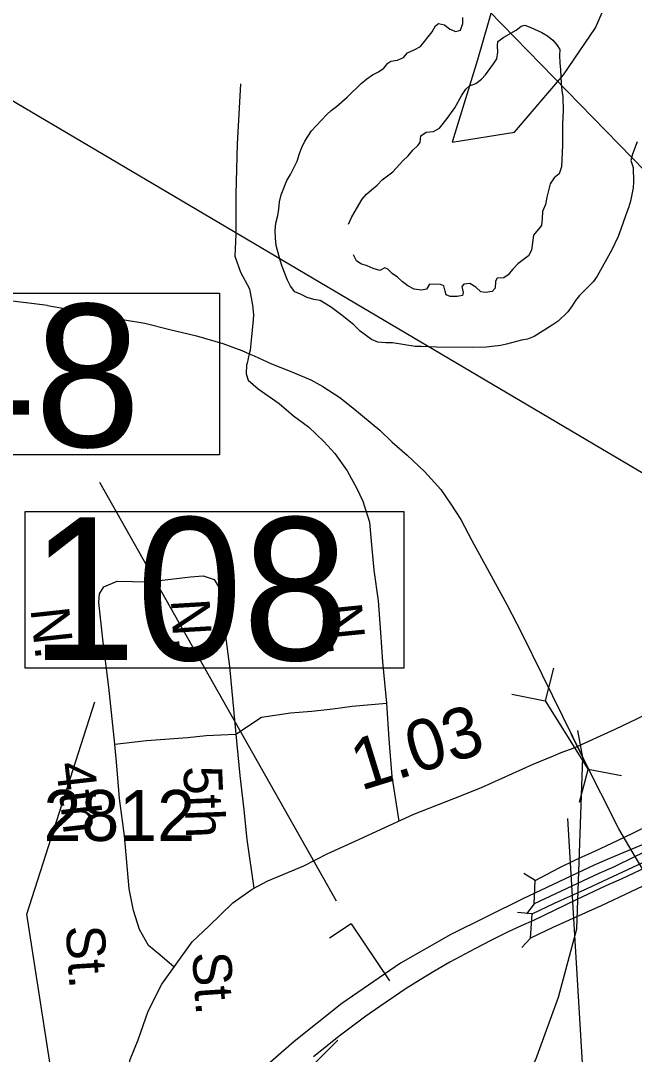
# Model space of a CAD drawing. Extents: x 2290055 to 2389491, y 66597 to 237875.
# Drawn here: x 2318095 to 2319601, y 184954 to 187491 of the extents above; entities that cross this region are included whole.
import ezdxf

# ---------------------------------------------------------------- set-up
doc = ezdxf.new("R2010")
doc.units = 0
for name, color, linetype in [('Exist Boundary Political City Limit New', 7, 'Continuous'), ('Exist Hydrographic Creek Double Shore', 7, 'Continuous'), ('Exist Hydrographic Island Shore', 7, 'Continuous'), ('Exist Railroad Mainline', 7, 'Continuous'), ('Exist Railroad Siding', 7, 'Continuous'), ('Exist Road Non-System Type 51', 7, 'Continuous'), ('Exist Road Non-System Type 51 Label', 7, 'Continuous'), ('Exist Road Primary US Divided Attributed', 7, 'Continuous'), ('Exist Road Primary US Ramp 1 Lane  Attributed', 7, 'Continuous'), ('Exist Road Primary US Structure Cantilever Sign CELL', 7, 'Continuous'), ('Exist Road Primary US Structure Cantilever Sign Number Label', 7, 'Continuous'), ('Exist Road Primary US Structure Standard Bridge Number Label', 7, 'Continuous'), ('Exist Road Secondary Mileage Hundredths English Label', 7, 'Continuous'), ('Exist Road Secondary Structure Culvert CELL', 7, 'Continuous'), ('Exist Road Secondary Type 51 Attributed', 7, 'Continuous'), ('Exist Road Secondary Type 51 Number Label', 7, 'Continuous'), ('Map Preparation Boundary City Limit Buffer Line', 7, 'Continuous')]:
    doc.layers.add(name, color=color, linetype=linetype)

msp = doc.modelspace()

# ---------------------------------------------------------------- linework, layer by layer
at = {"layer": 'Exist Boundary Political City Limit New'}
msp.add_lwpolyline([(2319108, 188879.4), (2319186.8, 188662.5), (2319224.5, 188585.7), (2319249.2, 188523.7), (2319282, 188432.2), (2319323.8, 188366.6), (2319377.2, 188199.9), (2319377.2, 188122.7), (2319369, 188044.2), (2319294.8, 187668), (2319216.2, 187395.2), (2319154.2, 187192.7), (2319307.2, 187217.5), (2319427, 187358), (2319505.5, 187473.8), (2319546.8, 187568.8), (2319601, 187700.6), (2319622.5, 187767.5)], dxfattribs=at)
at = {"layer": 'Exist Hydrographic Creek Double Shore'}
for points in [[(2319500.2, 186850.5), (2319477.5, 186827.3), (2319466.2, 186816.9), (2319456.5, 186804.8), (2319448.5, 186791.6), (2319438.2, 186776.8), (2319414, 186753.8), (2319399.2, 186743.6), (2319355, 186716.3), (2319339, 186709.4), (2319324, 186706.8), (2319287.7, 186697), (2319272.7, 186694.2), (2319238.7, 186689.9), (2319203, 186689.2), (2319115.7, 186690.1), (2319079, 186691.9), (2319063.7, 186691.8), (2319008, 186700.7), (2318991, 186700.8), (2318972, 186702.5), (2318956.2, 186709), (2318928.5, 186729.4), (2318912.5, 186745.1), (2318884.5, 186767.8), (2318858.2, 186787.5), (2318845, 186795.8), (2318830, 186804.2), (2318815, 186807.1), (2318798, 186811.5), (2318781.7, 186820), (2318768.2, 186825.8), (2318757.7, 186839.5), (2318750, 186854.5), (2318737.2, 186887.8), (2318731.7, 186903.1), (2318722.5, 186939.1), (2318720.5, 186957.7), (2318720, 186975.9), (2318721.2, 186994.5), (2318726, 187012.7), (2318729, 187028.9), (2318730.7, 187046.5), (2318734.2, 187064.1), (2318748.5, 187098.8), (2318757.5, 187113.3), (2318774, 187146.4), (2318779.5, 187165.1), (2318785, 187179.7), (2318792.7, 187195.1), (2318809.2, 187220.6), (2318845.5, 187260), (2318857.5, 187270.6), (2318870.5, 187280.5), (2318896.5, 187303.3), (2318931, 187337.2), (2318945, 187348.7), (2318959, 187357.9), (2318973.2, 187365.5), (2318986.7, 187374.2), (2318996.2, 187386.9), (2319003.5, 187391.4), (2319019.7, 187394.1), (2319034.5, 187400.8), (2319044.5, 187411.9), (2319061, 187419.8), (2319076, 187428), (2319105.2, 187464), (2319113.2, 187478.5), (2319120.7, 187483.9), (2319135.2, 187480.6), (2319148.2, 187470), (2319163, 187464.4), (2319174.7, 187468.1), (2319180.5, 187483.9), (2319180.5, 187499.2)], [(2319608.2, 187194), (2319596.5, 187163.6), (2319592.7, 187148.4), (2319598.2, 187131.2), (2319599, 187095.8), (2319598, 187080.9), (2319595, 187064.8), (2319591.5, 187048.2), (2319587, 187031.8), (2319580, 187014.6), (2319568.2, 186979.1), (2319561.5, 186961.7), (2319546.2, 186929), (2319509.5, 186863.8), (2319500.2, 186850.5)]]:
    msp.add_lwpolyline(points, dxfattribs=at)
at = {"layer": 'Exist Hydrographic Island Shore'}
msp.add_lwpolyline([(2318900, 186991.8), (2318907.7, 187010), (2318933.2, 187053), (2318943.7, 187065.1), (2318956.2, 187076.4), (2318969.7, 187087.3), (2318982.2, 187100.6), (2318995.7, 187110), (2319008.7, 187120.3), (2319032.7, 187147.1), (2319046.5, 187159.7), (2319057.2, 187173.6), (2319070, 187185), (2319075.5, 187192.3), (2319077.5, 187208.6), (2319090.5, 187217.6), (2319108.2, 187219.1), (2319123, 187227.1), (2319142, 187251), (2319161, 187277.4), (2319178.2, 187308.3), (2319187.7, 187322.7), (2319197, 187330.9), (2319212, 187336.9), (2319226, 187347.3), (2319236.2, 187358.5), (2319255.7, 187385), (2319263.5, 187397.9), (2319266.5, 187414.2), (2319265, 187429.5), (2319266.5, 187440.2), (2319281, 187450.7), (2319311.2, 187467.5), (2319323, 187477.4), (2319332.5, 187480.1), (2319347.5, 187474.4), (2319374.5, 187462.3), (2319387.7, 187454.3), (2319400.7, 187443.5), (2319410.5, 187431.9), (2319418, 187420.7), (2319417.5, 187405.5), (2319418, 187387.4), (2319420.2, 187370.7), (2319421.7, 187336.6), (2319423.2, 187319.6), (2319425.7, 187304), (2319426.7, 187269.7), (2319424.5, 187238.3), (2319424.5, 187185.7), (2319422, 187132.7), (2319416.7, 187115.4), (2319404.5, 187105.1), (2319394.7, 187090.8), (2319386.2, 187058.4), (2319383.2, 187040.1), (2319375.5, 187023.1), (2319375.2, 187006), (2319373.2, 186988.5), (2319353.7, 186964.5), (2319348.7, 186928.2), (2319341, 186913.8), (2319315, 186894.1), (2319302.5, 186880.8), (2319291.5, 186867.4), (2319280.5, 186860.3), (2319264.2, 186859.5), (2319260, 186851.8), (2319259.2, 186835), (2319252.2, 186826.8), (2319236.2, 186823.8), (2319224.2, 186825.5), (2319212.2, 186837.5), (2319197.2, 186845.9), (2319182.5, 186844.9), (2319177.7, 186839), (2319181.2, 186824), (2319179.2, 186816.6), (2319166, 186813.9), (2319149.2, 186814.5), (2319139.7, 186818.3), (2319136.7, 186827.6), (2319134, 186840.8), (2319125.7, 186843.5), (2319098.5, 186844.9), (2319090.7, 186832.5), (2319079, 186830), (2319061, 186832.6), (2319045.5, 186840.6), (2319032.5, 186850.4), (2319019.7, 186862), (2319007.2, 186870.8), (2318996.5, 186881.6), (2318988.5, 186884.9), (2318976.7, 186878.2), (2318960.5, 186882.9), (2318945.5, 186889.3), (2318930, 186894.1), (2318919.2, 186901.6), (2318912.2, 186916.3)], dxfattribs=at)
at = {"layer": 'Exist Railroad Mainline'}
msp.add_line((2319445.3, 185741.2), (2319475, 185682.8), dxfattribs=at)
for points in [[(2318160.9, 186791.8), (2318048.9, 186806.2), (2318015.4, 186810.7), (2317976, 186816), (2317895.2, 186827), (2317871.9, 186830.1), (2317679.1, 186856.1), (2317602.2, 186863.6), (2317520.3, 186871.6), (2317479.7, 186875.5), (2317393.9, 186883.8), (2316020.1, 187055.8)], [(2318160.9, 186791.8), (2318259.2, 186775.1), (2318349.7, 186757.3), (2318399.7, 186748.7), (2318458.3, 186733.8), (2318526.5, 186718.1), (2318591.7, 186699.3), (2318638.2, 186681.9), (2318656.2, 186673.8), (2318668.4, 186668.3), (2318710.8, 186649), (2318756.9, 186631.4), (2318807.4, 186609.4), (2318836.6, 186593.5), (2318878.7, 186566.6), (2318910.1, 186541.4), (2318976.7, 186486.3), (2319007.1, 186456.7), (2319043.6, 186425.1), (2319086.8, 186383.8), (2319126.6, 186340.4), (2319151, 186304.5), (2319175.5, 186266.9), (2319202.1, 186215.3), (2319245.2, 186137.8), (2319288.2, 186058.3), (2319325, 185986.9), (2319475, 185682.8)], [(2317368.7, 183162.4), (2317386.6, 183219.3), (2317454.9, 183335.6), (2317526.4, 183452.7), (2317687.4, 183621.9), (2317937.9, 183810.5), (2318299, 184030.9), (2318725.1, 184281.4), (2318969.1, 184431), (2319128.4, 184603.4), (2319252, 184736.8), (2319359.4, 184941.7), (2319414.7, 185094.6), (2319460.2, 185262.1), (2319475, 185682.8)], [(2319701.9, 185297.6), (2319667.3, 185337.3), (2319638.9, 185379), (2319604.1, 185438.4), (2319563.3, 185507.8), (2319475, 185682.8)]]:
    msp.add_lwpolyline(points, dxfattribs=at)
at = {"layer": 'Exist Railroad Siding'}
msp.add_line((2319475, 185682.8), (2319462.6, 185748.9), dxfattribs=at)
at = {"layer": 'Exist Road Non-System Type 51'}
for p, q in [((2318665.7, 186756.6), (2318660.8, 186706.9)), ((2318656.2, 186673.8), (2318650.8, 186650.7))]:
    msp.add_line(p, q, dxfattribs=at)
for points in [[(2318634.5, 187336.2), (2318626.4, 187187.8), (2318623.2, 187065.6), (2318623.1, 186967.6), (2318621.2, 186913.5), (2318634.8, 186874), (2318656.4, 186832.9), (2318664, 186793.2), (2318667, 186769.3), (2318665.7, 186756.6)], [(2318660.8, 186706.9), (2318658.4, 186682.9), (2318656.2, 186673.8)], [(2318650.8, 186650.7), (2318649.8, 186646.6), (2318648.7, 186624.5), (2318653.3, 186608.7), (2318678.2, 186587.7), (2318729.6, 186551.7), (2318764.8, 186521.1), (2318801.9, 186494.5), (2318839.4, 186458), (2318866.5, 186429.1), (2318896.2, 186386.2), (2318920, 186343.2), (2318935.2, 186311.8), (2318951.3, 186260.4), (2318954.8, 186222.5), (2318961.9, 186142.8), (2318972.9, 186067.2), (2318978, 185989.4), (2318982.9, 185917.5), (2318992.9, 185815.9)], [(2318326.3, 185715.6), (2318311.5, 185855.2), (2318298, 185965.8), (2318287.2, 186062.9), (2318288.6, 186084.5), (2318299.4, 186102), (2318331.7, 186115.5), (2318407.2, 186114.1), (2318463.8, 186120.9), (2318512.4, 186126.3), (2318543.4, 186129), (2318570.3, 186119.5), (2318582.5, 186099.3), (2318608.1, 185906.4), (2318623.6, 185740.5)], [(2318623.6, 185740.5), (2318686.1, 185781.7), (2318757.7, 185792.6), (2318809.6, 185796.6), (2318861.4, 185802.7), (2318909.1, 185808.6), (2318992.9, 185815.9)], [(2318992.9, 185815.9), (2318998.4, 185728.1), (2319006, 185636.4), (2319022.9, 185526.6)], [(2318326.3, 185715.6), (2318403.8, 185724.3), (2318504.9, 185731.7), (2318550.1, 185736.5), (2318586.5, 185738.5), (2318623.6, 185740.5)], [(2318623.6, 185740.5), (2318633, 185638.7), (2318643.1, 185554.4), (2318649.9, 185481.6), (2318667.5, 185362.1)], [(2318471.7, 185168.7), (2318436.9, 185198.3), (2318408.6, 185221.2), (2318387, 185260.4), (2318372.2, 185307.6), (2318361.4, 185360.2), (2318350.3, 185490.3), (2318338.1, 185582), (2318331, 185662.3), (2318326.3, 185715.6)]]:
    msp.add_lwpolyline(points, dxfattribs=at)
at = {"layer": 'Exist Road Primary US Divided Attributed'}
for p, q in [((2319357.9, 185380.8), (2319329.6, 185398.3)), ((2319355.1, 185323.7), (2319357.9, 185380.8)), ((2319355.1, 185323.7), (2319336.7, 185298.9)), ((2319350.6, 185299.3), (2319314.1, 185302.6)), ((2319346.3, 185239.4), (2319350.6, 185299.3)), ((2319346.3, 185239.4), (2319325.4, 185216.6))]:
    msp.add_line(p, q, dxfattribs=at)
for points in [[(2320712.1, 185997.5), (2320703.2, 185992.1), (2320647.9, 185960.4), (2320562, 185910.3), (2320527.2, 185891.4), (2320385, 185823.1), (2320340.5, 185800.2), (2320236.8, 185754.8), (2320164.8, 185720.6), (2320138.2, 185706.9), (2320050.4, 185668.4), (2319866.8, 185583), (2319830.5, 185565.9), (2319719.1, 185513.5), (2319649.9, 185480.8), (2319539.9, 185434.9), (2319504.1, 185419.5), (2319327.1, 185336.2), (2319150.5, 185248.7), (2319027.6, 185178.5), (2318883, 185079.4), (2318766.5, 184986.1), (2318676.8, 184907.3)], [(2319350.6, 185299.3), (2319405.1, 185325.7), (2319485.4, 185361.7), (2319523.9, 185379.1), (2319742.6, 185481.6), (2319817.9, 185516.4), (2319889, 185549.3), (2319964.4, 185583.8), (2320046.2, 185621.1), (2320100.7, 185651.8), (2320206.6, 185700), (2320301.8, 185745.7), (2320407.9, 185796.3), (2320490.2, 185834), (2320522, 185851.8), (2320604.3, 185894.5), (2320757.1, 185991.7)], [(2320742.8, 185999.2), (2320711.1, 185976), (2320653.8, 185943), (2320573.6, 185896.5), (2320534.3, 185876.4), (2320486.5, 185851.5), (2320395.6, 185808.8), (2320347.7, 185786.7), (2320292.2, 185760.5), (2320242.6, 185737.7), (2320175.9, 185706.9), (2320143.9, 185692.3), (2320062.3, 185654.1), (2320044, 185645.8), (2319996.2, 185625.1), (2319959.1, 185607.2), (2319874, 185568), (2319817.4, 185541.8), (2319726.2, 185499.4), (2319658.3, 185466.2), (2319601.6, 185439), (2319549.7, 185413.8), (2319513.9, 185398.4), (2319355.1, 185323.7)], [(2319357.9, 185380.8), (2319416.8, 185412.5), (2319456.5, 185431.5), (2319505.7, 185454.2), (2319559.5, 185479), (2319597.7, 185497.6), (2319640.4, 185518.3), (2319719.5, 185556.9), (2319881.4, 185637.9), (2319952.9, 185664.1), (2320053.8, 185696.4), (2320090.4, 185713.3), (2320155.8, 185743.9), (2320204.7, 185766.7), (2320259.5, 185792), (2320300.3, 185811.1), (2320334.3, 185826.9), (2320399.6, 185857.2), (2320450.9, 185880.9), (2320488.1, 185899.3), (2320539.7, 185926.3), (2320569.6, 185942.3), (2320624.9, 185974.5), (2320659.7, 185996.3)], [(2320675.7, 185879.6), (2320611.3, 185845.9), (2320510.1, 185795.3), (2320475.4, 185779.4), (2320401, 185743.7), (2320288.9, 185694.1), (2320203.6, 185655.4), (2320096.5, 185591.9), (2320041.9, 185561.2), (2319960.1, 185523.9), (2319884.7, 185489.4), (2319813.7, 185456.5), (2319738.3, 185421.7), (2319519.6, 185319.2), (2319481.2, 185301.8), (2319400.8, 185265.8), (2319346.3, 185239.4)], [(2319788.7, 185487.9), (2319570, 185385.4), (2319531.5, 185368), (2319458, 185333.2), (2319353.4, 185282.6), (2319323.5, 185269.4), (2319289.9, 185253.9), (2319250.3, 185234.4), (2319210, 185213.6), (2319148.1, 185180.4), (2319109, 185157.5), (2319075.5, 185137.4), (2319041, 185115.7), (2318976.3, 185072.1), (2318942.5, 185048.3), (2318876.6, 184998.9), (2318814.1, 184948.5)]]:
    msp.add_lwpolyline(points, dxfattribs=at)
at = {"layer": 'Exist Road Primary US Ramp 1 Lane  Attributed'}
msp.add_lwpolyline([(2318745, 184861.8), (2318873.5, 184988.9)], dxfattribs=at)
at = {"layer": 'Exist Road Primary US Structure Cantilever Sign CELL'}
for q in [(2318853.4, 185239.7), (2319000, 185134.9)]:
    msp.add_line((2318906.1, 185275), q, dxfattribs=at)
at = {"layer": 'Exist Road Primary US Structure Cantilever Sign Number Label'}
msp.add_line((2318870.4, 185330.6), (2318289.5, 186357.4), dxfattribs=at)
msp.add_lwpolyline([(2317336.2, 186822.2), (2318583.1, 186822.2), (2318583.1, 186425.5), (2317336.2, 186425.5)], close=True, dxfattribs=at)
at = {"layer": 'Exist Road Primary US Structure Standard Bridge Number Label'}
for p, q in [((2320485.8, 186238.6), (2319101.1, 187662.6)), ((2320426.9, 185904.7), (2318050.3, 187309))]:
    msp.add_line(p, q, dxfattribs=at)
msp.add_lwpolyline([(2318106.4, 186286.2), (2319035.4, 186286.2), (2319035.4, 185902.1), (2318106.4, 185902.1)], close=True, dxfattribs=at)
for points in [[(2318269.8, 184271.2), (2318110.7, 185298.6), (2318277.1, 185819.6)], [(2319437, 185533.3), (2319477.5, 184864.5), (2320232, 184163.7)]]:
    msp.add_lwpolyline(points, dxfattribs=at)
at = {"layer": 'Exist Road Secondary Structure Culvert CELL'}
for p, q in [((2319402.9, 185902.4), (2319382.2, 185821.8)), ((2319300.5, 185838.1), (2319382.2, 185821.8)), ((2319382.2, 185821.8), (2319487.7, 185653.8)), ((2319466.9, 185573.1), (2319487.7, 185653.8)), ((2319569.3, 185637.5), (2319487.7, 185653.8))]:
    msp.add_line(p, q, dxfattribs=at)
at = {"layer": 'Exist Road Secondary Type 51 Attributed'}
for points in [[(2319453.3, 185706.6), (2319554.4, 185752.2), (2319607.2, 185777.7), (2319779.2, 185861.4), (2319840.4, 185893.2), (2319906.2, 185931.8), (2319951.5, 185970.4), (2319996.9, 186011.2), (2320040, 186047.5), (2320101.2, 186115.6), (2320185.1, 186219.9), (2320210, 186269.8), (2320280.3, 186385.6), (2320358.3, 186498.3), (2320406.4, 186578.1), (2320614.1, 186893)], [(2318348, 184835.5), (2318348.2, 184837.5), (2318354.1, 184885.5), (2318364.3, 184941.7), (2318383.6, 184990.1), (2318408.4, 185060.5), (2318441.3, 185126.3), (2318516.2, 185230.7), (2318557, 185269.3), (2318615.9, 185326), (2318663.6, 185360), (2318702.1, 185380.4), (2318790.5, 185416.7), (2318847.2, 185446.2), (2318917.5, 185478), (2319060.4, 185543.8), (2319157.9, 185582.4), (2319225.9, 185609.6), (2319352.9, 185666.3), (2319402.8, 185686.7), (2319421.4, 185694.8), (2319453.3, 185706.6)]]:
    msp.add_lwpolyline(points, dxfattribs=at)
at = {"layer": 'Map Preparation Boundary City Limit Buffer Line'}
msp.add_lwpolyline([(2319108, 188879.4), (2319186.8, 188662.5), (2319224.5, 188585.7), (2319249.2, 188523.7), (2319282, 188432.2), (2319323.8, 188366.6), (2319377.2, 188199.9), (2319377.2, 188122.7), (2319369, 188044.2), (2319294.8, 187668), (2319216.2, 187395.2), (2319154.2, 187192.7), (2319307.2, 187217.5), (2319427, 187358), (2319505.5, 187473.8), (2319546.8, 187568.8), (2319601, 187700.6), (2319622.5, 187767.5)], dxfattribs=at)

# ---------------------------------------------------------------- texts
at = {"layer": 'Exist Road Non-System Type 51 Label'}
for s, rotation, p in [('N.', 276.2166, (2318119, 186047.3)), ('N.', 273.4186, (2318463.7, 186070.1)), ('N.', 275.7187, (2318837.3, 186057.8)), ('4th', 276.5907, (2318181.3, 185668)), ('5th', 272.269, (2318494.5, 185660.6)), ('St.', 273.6351, (2318205.7, 185268.6)), ('St.', 273.8186, (2318515.9, 185203.6))]:
    msp.add_text(s, height=95, rotation=rotation, dxfattribs=at).set_placement(p)
at = {"layer": 'Exist Road Primary US Structure Cantilever Sign Number Label'}
msp.add_text('L148', height=350, dxfattribs=at).set_placement((2317348.7, 186445.3))
at = {"layer": 'Exist Road Primary US Structure Standard Bridge Number Label'}
msp.add_text('108', height=350, dxfattribs=at).set_placement((2318119, 185921.9))
at = {"layer": 'Exist Road Secondary Mileage Hundredths English Label'}
msp.add_text('1.03', height=125, rotation=17.1441, dxfattribs=at).set_placement((2318929.7, 185600.9))
at = {"layer": 'Exist Road Secondary Type 51 Number Label'}
msp.add_text('2812', height=125, dxfattribs=at).set_placement((2318151.2, 185478.1))

doc.saveas('drawing.dxf')
